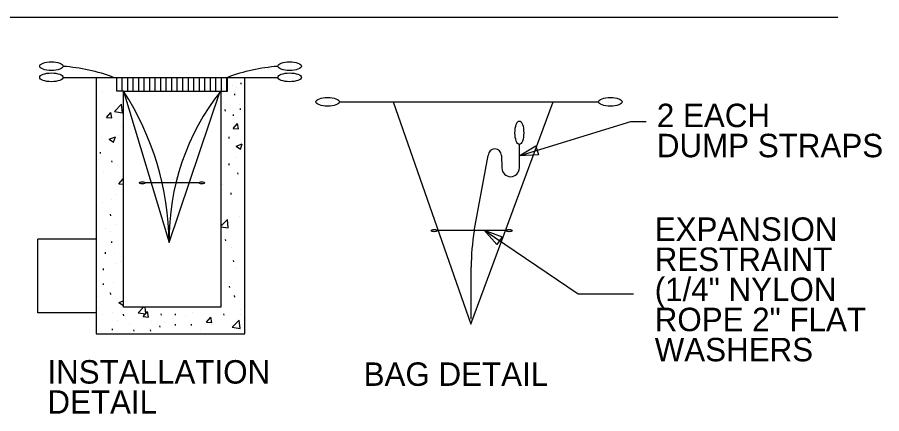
# Model space of a CAD drawing. Extents: x 10109 to 10183.6, y 10015.3 to 10070.3.
# Drawn here: x 10144.72 to 10183.24, y 10052.6 to 10070.26 of the extents above; entities that cross this region are included whole.
import ezdxf

# ---------------------------------------------------------------- set-up
doc = ezdxf.new("R2010")
doc.units = 0
for name, color, linetype in [('Default', 7, 'Continuous'), ('G-ANNO-DIMS', 7, 'Continuous'), ('G-ANNO-TEXT', 7, 'Continuous'), ('G-ANNO-TTXT', 7, 'Continuous'), ('G-DETL-LINE', 7, 'Continuous'), ('G-DETL-OTLN', 7, 'Continuous'), ('G-DETL-PATT', 7, 'Continuous')]:
    doc.layers.add(name, color=color, linetype=linetype)

# ---------------------------------------------------------------- blocks, each defined once
blk = doc.blocks.new('TERARR')
at = {"layer": 'Default'}
blk.add_lwpolyline([(-0.667, 0.167), (0, 0), (-0.667, -0.167)], close=True, dxfattribs=at)

msp = doc.modelspace()

# ---------------------------------------------------------------- linework, layer by layer
at = {"layer": 'Default'}
for p, q in [((10149.287, 10066.282), (10149.287, 10066.282)), ((10154.853, 10062.929), (10154.853, 10062.929)), ((10153.818, 10061.378), (10153.818, 10061.378)), ((10149.449, 10057.415), (10149.455, 10057.432))]:
    msp.add_line(p, q, dxfattribs=at)
at = {"layer": 'G-ANNO-DIMS'}
msp.add_line((10154.066, 10066.971), (10154.066, 10067.582), dxfattribs=at)
at = {"layer": 'G-ANNO-TEXT'}
for points in [[(10167.088, 10064.089), (10172.059, 10065.612), (10172.753, 10065.612)], [(10165.527, 10060.778), (10169.714, 10057.933), (10172.187, 10057.933)]]:
    msp.add_lwpolyline(points, dxfattribs=at)
at = {"layer": 'G-ANNO-TTXT'}
for p, q in [((10148.24, 10067.582), (10149.154, 10067.582)), ((10154.09, 10067.582), (10154.86, 10067.582))]:
    msp.add_line(p, q, dxfattribs=at)
at = {"layer": 'G-DETL-LINE'}
for p, q in [((10108.968, 10070.256), (10181.284, 10070.256)), ((10146.766, 10067.582), (10156.335, 10067.582)), ((10149.455, 10066.971), (10151.494, 10060.228)), ((10151.494, 10060.228), (10153.764, 10066.971)), ((10159.076, 10066.492), (10170.629, 10066.492)), ((10161.471, 10066.492), (10164.931, 10056.59)), ((10164.931, 10056.59), (10168.604, 10066.492)), ((10152.841, 10062.882), (10150.409, 10062.882)), ((10166.543, 10060.755), (10163.404, 10060.755)), ((10145.634, 10057.096), (10145.634, 10060.376)), ((10148.24, 10060.375), (10145.634, 10060.376)), ((10148.24, 10057.089), (10145.634, 10057.096))]:
    msp.add_line(p, q, dxfattribs=at)
for points in [[(10167.096, 10063.547), (10167.096, 10064.591)], [(10165.085, 10060.746), (10165.71, 10064.1)], [(10166.3, 10064.1), (10166.316, 10063.547)], [(10164.951, 10056.817), (10164.951, 10059.129)]]:
    msp.add_lwpolyline(points, dxfattribs=at)
for centre, radius, start, end in [((10146.134, 10059.756), 8.338, 69.7691, 85.6565), ((10156.967, 10059.756), 8.338, 94.3435, 110.2309), ((10138.804, 10060.069), 12.691, 0.7142, 32.9425), ((10162.003, 10060.406), 10.51, 141.3468, 180.9723), ((10166.005, 10064.1), 0.295, 0, 180), ((10166.706, 10063.547), 0.39, 180, 0), ((10174.782, 10059.129), 9.83, 170.5298, 180)]:
    msp.add_arc(centre, radius, start, end, dxfattribs=at)
for centre, major_axis in [((10146.243, 10068.081), (-0.523, 0)), ((10156.858, 10068.081), (-0.523, 0)), ((10146.243, 10067.582), (-0.523, 0)), ((10156.858, 10067.582), (-0.523, 0)), ((10158.553, 10066.492), (-0.523, 0)), ((10171.152, 10066.492), (-0.523, 0)), ((10167.096, 10065.114), (0, -0.523)), ((10150.296, 10062.881), (-0.131, 0)), ((10152.945, 10062.881), (-0.131, 0)), ((10163.302, 10060.754), (-0.131, 0)), ((10166.644, 10060.754), (-0.131, 0))]:
    msp.add_ellipse(centre, major_axis=major_axis, ratio=0.374964, dxfattribs=at)
at = {"layer": 'G-DETL-OTLN'}
for p, q in [((10148.24, 10067.582), (10148.24, 10056.164)), ((10149.154, 10066.971), (10149.154, 10067.582)), ((10154.09, 10066.971), (10154.09, 10067.582)), ((10154.86, 10056.164), (10154.86, 10067.582)), ((10149.455, 10066.971), (10149.154, 10066.971)), ((10149.455, 10057.349), (10149.455, 10066.971)), ((10149.455, 10066.971), (10153.764, 10066.971)), ((10153.795, 10066.971), (10154.09, 10066.971)), ((10153.795, 10066.971), (10153.795, 10057.349)), ((10153.795, 10057.349), (10149.455, 10057.349)), ((10148.24, 10056.164), (10154.86, 10056.164))]:
    msp.add_line(p, q, dxfattribs=at)
at = {"layer": 'G-DETL-PATT'}
for p, q in [((10149.396, 10066.971), (10149.396, 10067.582)), ((10149.642, 10066.971), (10149.642, 10067.582)), ((10149.888, 10066.971), (10149.888, 10067.582)), ((10150.134, 10066.971), (10150.134, 10067.582)), ((10150.379, 10066.971), (10150.379, 10067.582)), ((10150.625, 10066.971), (10150.625, 10067.582)), ((10150.871, 10066.971), (10150.871, 10067.582)), ((10151.117, 10066.971), (10151.117, 10067.582)), ((10151.362, 10066.971), (10151.362, 10067.582)), ((10151.608, 10066.971), (10151.608, 10067.582)), ((10151.854, 10066.971), (10151.854, 10067.582)), ((10152.1, 10066.971), (10152.1, 10067.582)), ((10152.345, 10066.971), (10152.345, 10067.582)), ((10152.591, 10066.971), (10152.591, 10067.582)), ((10152.837, 10066.971), (10152.837, 10067.582)), ((10153.083, 10066.971), (10153.083, 10067.582)), ((10153.328, 10066.971), (10153.328, 10067.582)), ((10153.574, 10066.971), (10153.574, 10067.582)), ((10153.82, 10066.971), (10153.82, 10067.582)), ((10154.315, 10067.219), (10154.315, 10067.219)), ((10154.488, 10067.125), (10154.488, 10067.125)), ((10154.68, 10067.343), (10154.687, 10067.278)), ((10148.529, 10066.968), (10148.529, 10066.968)), ((10154.402, 10066.846), (10154.409, 10066.781)), ((10149.059, 10066.061), (10149.366, 10066.381)), ((10149.409, 10066.007), (10149.366, 10066.38)), ((10154.617, 10066.379), (10154.617, 10066.379)), ((10148.7, 10065.797), (10148.89, 10066.023)), ((10148.936, 10065.776), (10148.89, 10066.023)), ((10149.059, 10066.061), (10149.409, 10066.007)), ((10153.978, 10066.143), (10153.985, 10066.079)), ((10154.655, 10066.199), (10154.662, 10066.134)), ((10148.7, 10065.797), (10148.935, 10065.777)), ((10154.336, 10065.931), (10154.343, 10065.866)), ((10149.351, 10065.387), (10149.351, 10065.387)), ((10154.341, 10065.304), (10154.531, 10065.53)), ((10154.341, 10065.304), (10154.576, 10065.283)), ((10154.576, 10065.283), (10154.531, 10065.529)), ((10148.497, 10064.921), (10148.497, 10064.921)), ((10148.819, 10064.833), (10149.095, 10064.938)), ((10148.819, 10064.833), (10149.015, 10064.701)), ((10149.015, 10064.701), (10149.095, 10064.938)), ((10149.239, 10064.973), (10149.239, 10064.973)), ((10154.145, 10064.928), (10154.152, 10064.863)), ((10154.378, 10064.681), (10154.378, 10064.681)), ((10154.47, 10064.518), (10154.746, 10064.624)), ((10154.47, 10064.518), (10154.666, 10064.386)), ((10154.666, 10064.386), (10154.746, 10064.623)), ((10148.413, 10064.25), (10148.42, 10064.185)), ((10154.455, 10064.033), (10154.455, 10064.033)), ((10148.925, 10063.866), (10148.932, 10063.801)), ((10149.191, 10063.664), (10149.191, 10063.664)), ((10154.145, 10063.738), (10154.152, 10063.673)), ((10148.569, 10063.388), (10148.569, 10063.388)), ((10154.542, 10063.328), (10154.549, 10063.263)), ((10149.246, 10062.839), (10149.436, 10063.065)), ((10149.455, 10062.963), (10149.436, 10063.065)), ((10149.246, 10062.839), (10149.455, 10062.821)), ((10153.868, 10062.799), (10153.868, 10062.799)), ((10148.911, 10062.147), (10148.911, 10062.147)), ((10149.143, 10062.355), (10149.143, 10062.355)), ((10154.234, 10062.432), (10154.242, 10062.367)), ((10148.517, 10061.988), (10148.517, 10061.988)), ((10148.864, 10061.483), (10148.872, 10061.418)), ((10154.605, 10061.4), (10154.605, 10061.4)), ((10149.096, 10061.046), (10149.096, 10061.046)), ((10153.795, 10060.948), (10154.084, 10061.249)), ((10154.127, 10060.875), (10154.084, 10061.248)), ((10154.1, 10061.113), (10154.1, 10061.113)), ((10148.632, 10060.85), (10148.632, 10060.85)), ((10148.861, 10060.725), (10148.861, 10060.725)), ((10153.795, 10060.927), (10154.127, 10060.875)), ((10148.916, 10060.276), (10148.923, 10060.211)), ((10153.991, 10060.358), (10153.999, 10060.294)), ((10148.638, 10059.793), (10148.645, 10059.728)), ((10154.273, 10060.023), (10154.273, 10060.023)), ((10149.048, 10059.737), (10149.048, 10059.737)), ((10154.35, 10059.424), (10154.357, 10059.359)), ((10148.543, 10059.062), (10148.55, 10058.997)), ((10149.12, 10059.291), (10149.12, 10059.291)), ((10149.316, 10059.37), (10149.316, 10059.37)), ((10154.443, 10059.053), (10154.443, 10059.053)), ((10148.543, 10058.403), (10148.55, 10058.338)), ((10149, 10058.428), (10149, 10058.428)), ((10154.171, 10058.285), (10154.178, 10058.22)), ((10148.864, 10057.979), (10148.872, 10057.914)), ((10154.388, 10057.862), (10154.395, 10057.797)), ((10148.282, 10057.82), (10148.282, 10057.82)), ((10149.253, 10057.547), (10149.455, 10057.624)), ((10149.253, 10057.547), (10149.449, 10057.415)), ((10148.354, 10057.282), (10148.354, 10057.282)), ((10148.952, 10057.119), (10148.952, 10057.119)), ((10150.102, 10057.099), (10150.342, 10057.349)), ((10150.102, 10057.099), (10150.452, 10057.045)), ((10150.337, 10056.924), (10150.527, 10057.15)), ((10150.452, 10057.044), (10150.416, 10057.349)), ((10150.453, 10057.193), (10150.453, 10057.193)), ((10150.572, 10056.903), (10150.527, 10057.15)), ((10152.552, 10057.104), (10152.552, 10057.104)), ((10154.688, 10057.248), (10154.688, 10057.248)), ((10148.506, 10057.009), (10148.506, 10057.009)), ((10149.183, 10056.754), (10149.183, 10056.754)), ((10149.448, 10057.03), (10149.455, 10056.965)), ((10150.337, 10056.924), (10150.572, 10056.903)), ((10150.715, 10056.725), (10150.715, 10056.725)), ((10151.126, 10057.056), (10151.133, 10056.991)), ((10151.752, 10057.056), (10151.76, 10056.991)), ((10152.204, 10056.921), (10152.204, 10056.921)), ((10153.158, 10056.677), (10153.347, 10056.903)), ((10153.393, 10056.656), (10153.347, 10056.903)), ((10153.915, 10057.056), (10153.922, 10056.991)), ((10154.299, 10056.448), (10154.605, 10056.767)), ((10154.648, 10056.394), (10154.605, 10056.767)), ((10154.651, 10057.016), (10154.651, 10057.016)), ((10148.944, 10056.379), (10148.951, 10056.314)), ((10149.731, 10056.596), (10149.731, 10056.596)), ((10149.901, 10056.342), (10149.909, 10056.277)), ((10150.647, 10056.342), (10150.654, 10056.277)), ((10151.064, 10056.518), (10151.071, 10056.453)), ((10151.282, 10056.665), (10151.282, 10056.665)), ((10151.752, 10056.595), (10151.76, 10056.53)), ((10152.469, 10056.595), (10152.476, 10056.53)), ((10152.909, 10056.339), (10152.909, 10056.339)), ((10153.158, 10056.677), (10153.393, 10056.657)), ((10153.381, 10056.576), (10153.381, 10056.576)), ((10154.299, 10056.448), (10154.648, 10056.394)), ((10154.594, 10056.42), (10154.594, 10056.42))]:
    msp.add_line(p, q, dxfattribs=at)

# ---------------------------------------------------------------- block references
at = {"layer": 'G-ANNO-TEXT'}
for p, xscale, yscale, rotation in [((10167.088, 10064.089), 1.2499200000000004, 1.2499199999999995, -162.9617027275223), ((10165.527, 10060.778), 1.24992, 1.24992, 145.80432427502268)]:
    msp.add_blockref('TERARR', p, dxfattribs=dict(at, xscale=xscale, yscale=yscale, rotation=rotation))

# ---------------------------------------------------------------- texts
for s, p in [('2 EACH', (10173.224, 10065.364)), ('DUMP STRAPS', (10173.224, 10064.023)), ('EXPANSION', (10173.128, 10060.299)), ('RESTRAINT', (10173.128, 10058.958)), ('(1/4" NYLON', (10173.128, 10057.617)), ('ROPE 2" FLAT', (10173.128, 10056.276)), ('WASHERS', (10173.128, 10054.935)), ('INSTALLATION', (10146.064, 10053.942)), ('BAG DETAIL', (10160.157, 10053.841)), ('DETAIL', (10146.064, 10052.601))]:
    msp.add_text(s, height=1.044, dxfattribs=at).set_placement(p)

doc.saveas('drawing.dxf')
